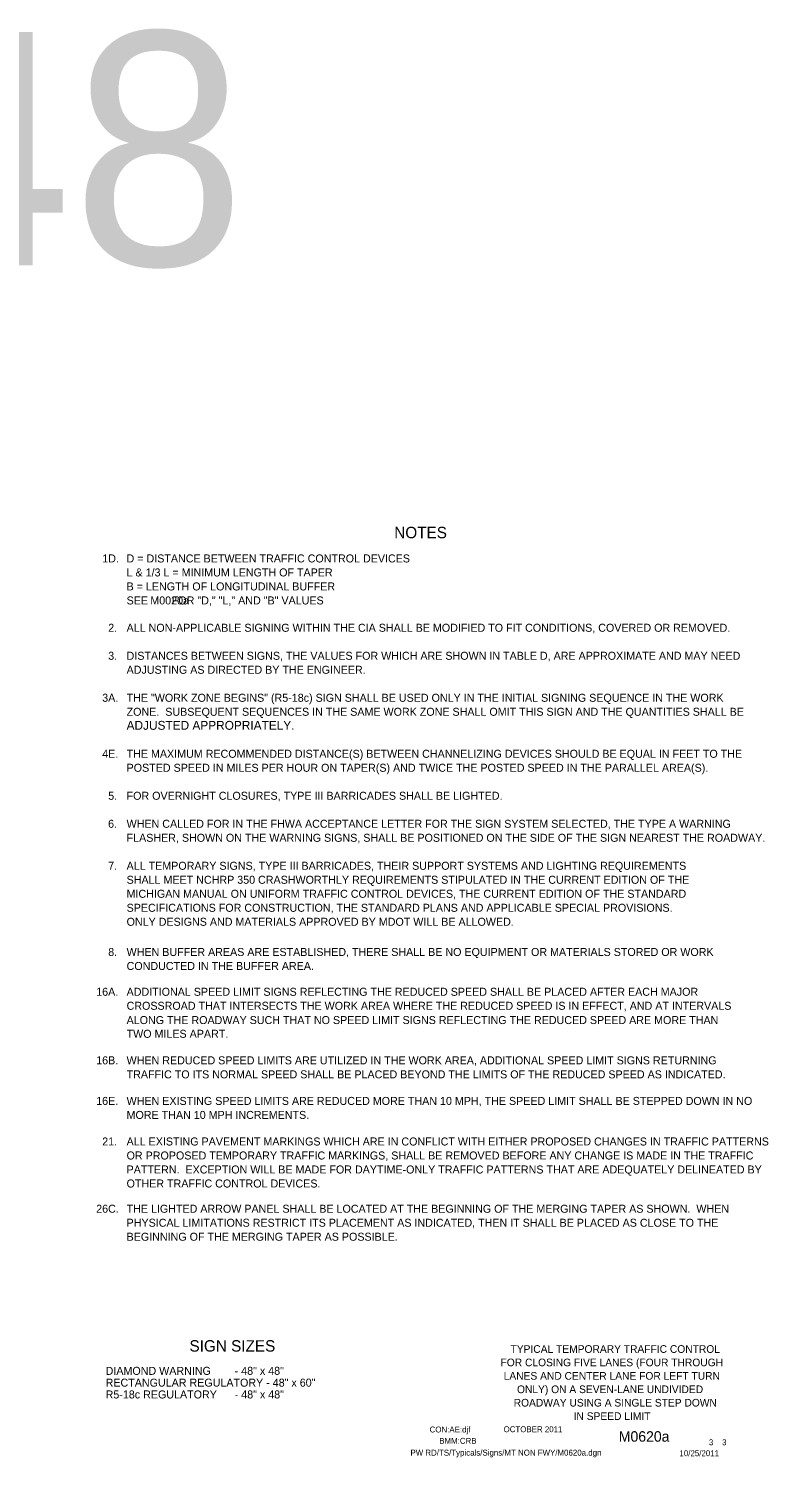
# Model space of a CAD drawing. Extents: x 20837 to 23689, y 414 to 2167.
# Drawn here: x 22912 to 23689, y 667 to 2167 of the extents above; entities that cross this region are included whole.
import ezdxf

# ---------------------------------------------------------------- set-up
doc = ezdxf.new("R2010")
doc.units = 0
for name, color, linetype in [('BORDER', 7, 'Continuous'), ('BORDER_SIGNAL_WO', 7, 'Continuous'), ('TYPICAL_TEXT_DIMEN_PR', 7, 'Continuous')]:
    doc.layers.add(name, color=color, linetype=linetype)

msp = doc.modelspace()

# ---------------------------------------------------------------- linework, layer by layer
at = {"layer": 'BORDER'}
msp.add_line((23531.6, 746.5), (23531.6, 746.5), dxfattribs=at)
msp.add_line((23531.6, 746.5), (23531.6, 746.5), dxfattribs=at)
at = {"layer": 'BORDER_SIGNAL_WO'}
msp.add_line((23531.6, 740.2), (23531.6, 740.2), dxfattribs=at)

# ---------------------------------------------------------------- texts
for s, height, p in [('TYPICAL TEMPORARY TRAFFIC CONTROL', 8.039, (23417.9, 776.9)), ('FOR CLOSING FIVE LANES (FOUR THROUGH', 8.039, (23407.4, 762.8)), ('LANES AND CENTER LANE FOR LEFT TURN', 8.039, (23410.7, 748.7)), ('ONLY) ON A SEVEN-LANE UNDIVIDED', 8.039, (23424.7, 734.6)), ('ROADWAY USING A SINGLE STEP DOWN', 8.039, (23421.2, 720.5)), ('IN SPEED LIMIT', 8.039, (23484.1, 706.4)), ('CON:AE:djf', 6.2, (23333, 693.3)), ('    OCTOBER 2011    ', 6.2, (23401.4, 693.6)), ('    M0620a   ', 11, (23515.2, 683.6)), ('PW RD/TS/Typicals/Signs/MT NON FWY/M0620a.dgn    ', 6.2, (23312.9, 669)), ('BMM:CRB   ', 6.2, (23343.1, 681.4)), (' 3    3 ', 6.2, (23623.8, 679.9)), ('10/25/2011    ', 6.2, (23595.2, 668.4))]:
    msp.add_text(s, height=height, dxfattribs=at).set_placement(p)
at = {"layer": 'TYPICAL_TEXT_DIMEN_PR'}
for s, height, p in [('M 48', 245.04, (22411.4, 1918.7)), ('NOTES', 12, (23295.9, 1632.2)), ('1D.', 8.4, (22989.5, 1606.8)), ('D = DISTANCE BETWEEN TRAFFIC CONTROL DEVICES', 8.4, (23015, 1606.8)), ('L & 1/3 L = MINIMUM LENGTH OF TAPER', 8.4, (23015, 1592.1)), ('B = LENGTH OF LONGITUDINAL BUFFER', 8.4, (23015, 1577.4)), ('SEE        FOR "D," "L," AND "B" VALUES', 8.4, (23015, 1562.7)), ('M0020a', 8.4, (23039.9, 1562.7)), ('2.', 8.4, (22995.7, 1534)), ('ALL NON-APPLICABLE SIGNING WITHIN THE CIA SHALL BE MODIFIED TO FIT CONDITIONS, COVERED OR REMOVED.', 8.4, (23015, 1534)), ('3.', 8.4, (22995.7, 1504.6)), ('DISTANCES BETWEEN SIGNS, THE VALUES FOR WHICH ARE SHOWN IN TABLE D, ARE APPROXIMATE AND MAY NEED', 8.4, (23015, 1504.6)), ('ADJUSTING AS DIRECTED BY THE ENGINEER.', 8.4, (23015, 1489.9)), ('3A.', 8.4, (22989.4, 1460.5)), ('THE "WORK ZONE BEGINS" (R5-18c) SIGN SHALL BE USED ONLY IN THE INITIAL SIGNING SEQUENCE IN THE WORK', 8.4, (23015, 1460.5)), ('ADJUSTED APPROPRIATELY.', 9.3, (23015, 1431.1)), ('ZONE.  SUBSEQUENT SEQUENCES IN THE SAME WORK ZONE SHALL OMIT THIS SIGN AND THE QUANTITIES SHALL BE', 8.4, (23015, 1445.8)), ('THE MAXIMUM RECOMMENDED DISTANCE(S) BETWEEN CHANNELIZING DEVICES SHOULD BE EQUAL IN FEET TO THE', 8.4, (23015, 1401.7)), ('4E.', 8.4, (22989.4, 1401.7)), ('POSTED SPEED IN MILES PER HOUR ON TAPER(S) AND TWICE THE POSTED SPEED IN THE PARALLEL AREA(S).', 8.4, (23015, 1387)), ('5.', 8.4, (22995.7, 1357.6)), ('FOR OVERNIGHT CLOSURES, TYPE III BARRICADES SHALL BE LIGHTED.', 8.4, (23015, 1357.6)), ('6.', 8.4, (22995.6, 1328.2)), ('WHEN CALLED FOR IN THE FHWA ACCEPTANCE LETTER FOR THE SIGN SYSTEM SELECTED, THE TYPE A WARNING ', 8.4, (23015, 1328.2)), ('FLASHER, SHOWN ON THE WARNING SIGNS, SHALL BE POSITIONED ON THE SIDE OF THE SIGN NEAREST THE ROADWAY.', 8.4, (23015, 1313.5)), ('7.', 8.4, (22995.7, 1284.1)), ('ALL TEMPORARY SIGNS, TYPE III BARRICADES, THEIR SUPPORT SYSTEMS AND LIGHTING REQUIREMENTS', 8.4, (23015, 1284.1)), ('SHALL MEET NCHRP 350 CRASHWORTHLY REQUIREMENTS STIPULATED IN THE CURRENT EDITION OF THE', 8.4, (23015, 1269.4)), ('MICHIGAN MANUAL ON UNIFORM TRAFFIC CONTROL DEVICES, THE CURRENT EDITION OF THE STANDARD', 8.4, (23015, 1254.7)), ('SPECIFICATIONS FOR CONSTRUCTION, THE STANDARD PLANS AND APPLICABLE SPECIAL PROVISIONS.', 8.4, (23015, 1240)), ('ONLY DESIGNS AND MATERIALS APPROVED BY MDOT WILL BE ALLOWED.', 8.4, (23015, 1225.3)), ('8.', 8.4, (22995.7, 1193.6)), ('WHEN BUFFER AREAS ARE ESTABLISHED, THERE SHALL BE NO EQUIPMENT OR MATERIALS STORED OR WORK     ', 8.4, (23015, 1193.6)), ('CONDUCTED IN THE BUFFER AREA.', 8.4, (23015, 1178.9)), ('16A.', 8.4, (22983.1, 1151.8)), ('ADDITIONAL SPEED LIMIT SIGNS REFLECTING THE REDUCED SPEED SHALL BE PLACED AFTER EACH MAJOR', 8.4, (23015, 1151.8)), ('CROSSROAD THAT INTERSECTS THE WORK AREA WHERE THE REDUCED SPEED IS IN EFFECT, AND AT INTERVALS', 8.4, (23015, 1137.1)), ('ALONG THE ROADWAY SUCH THAT NO SPEED LIMIT SIGNS REFLECTING THE REDUCED SPEED ARE MORE THAN', 8.4, (23015, 1122.1)), ('TWO MILES APART.', 8.4, (23015, 1107.7)), ('16B.', 8.4, (22983.1, 1079.8)), ('WHEN REDUCED SPEED LIMITS ARE UTILIZED IN THE WORK AREA, ADDITIONAL SPEED LIMIT SIGNS RETURNING', 8.4, (23015, 1079.8)), ('TRAFFIC TO ITS NORMAL SPEED SHALL BE PLACED BEYOND THE LIMITS OF THE REDUCED SPEED AS INDICATED.', 8.4, (23015, 1065.1)), ('16E.', 8.4, (22983.1, 1037.2)), ('WHEN EXISTING SPEED LIMITS ARE REDUCED MORE THAN 10 MPH, THE SPEED LIMIT SHALL BE STEPPED DOWN IN NO', 8.4, (23015, 1037.2)), ('MORE THAN 10 MPH INCREMENTS.', 8.4, (23015, 1022.5)), ('21.', 8.4, (22989.4, 994.6)), ('ALL EXISTING PAVEMENT MARKINGS WHICH ARE IN CONFLICT WITH EITHER PROPOSED CHANGES IN TRAFFIC PATTERNS', 8.4, (23015, 994.6)), ('OR PROPOSED TEMPORARY TRAFFIC MARKINGS, SHALL BE REMOVED BEFORE ANY CHANGE IS MADE IN THE TRAFFIC', 8.4, (23015, 979.9)), ('PATTERN.  EXCEPTION WILL BE MADE FOR DAYTIME-ONLY TRAFFIC PATTERNS THAT ARE ADEQUATELY DELINEATED BY', 8.4, (23015, 965.2)), ('OTHER TRAFFIC CONTROL DEVICES.', 8.4, (23015, 950.5)), ('26C.', 8.4, (22983.1, 924)), ('THE LIGHTED ARROW PANEL SHALL BE LOCATED AT THE BEGINNING OF THE MERGING TAPER AS SHOWN.  WHEN', 8.4, (23015, 924)), ('PHYSICAL LIMITATIONS RESTRICT ITS PLACEMENT AS INDICATED, THEN IT SHALL BE PLACED AS CLOSE TO THE', 8.4, (23015, 909.3)), ('BEGINNING OF THE MERGING TAPER AS POSSIBLE.', 8.4, (23015, 894.6)), ('SIGN SIZES', 12, (23081, 778.2)), ('DIAMOND WARNING        - 48" x 48"', 8.4, (22993, 753.8)), ('RECTANGULAR REGULATORY - 48" x 60"', 8.4, (22993, 741.4)), ('R5-18c REGULATORY      - 48" x 48"', 8.4, (22993, 729))]:
    msp.add_text(s, height=height, dxfattribs=at).set_placement(p)

doc.saveas('drawing.dxf')
